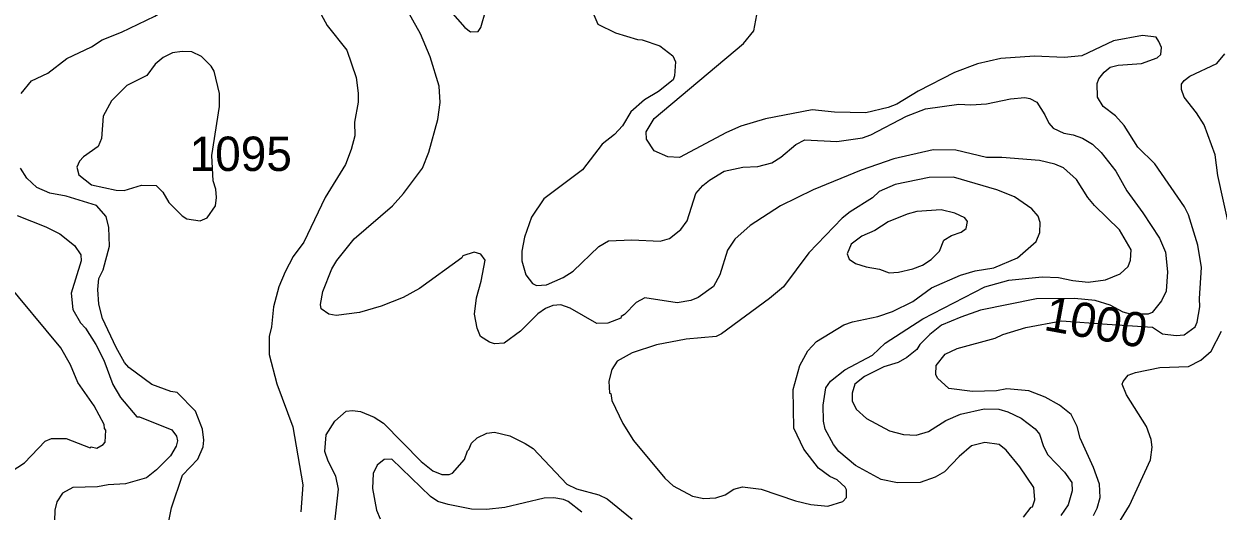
# Model space of a CAD drawing. Extents: x 447.8 to 473.9, y 7733.1 to 7760.8.
# Drawn here: x 464.533 to 467.311, y 7752.592 to 7753.726 of the extents above; entities that cross this region are included whole.
import ezdxf
from ezdxf.enums import TextEntityAlignment as Align

# ---------------------------------------------------------------- set-up
doc = ezdxf.new("R2010")
doc.units = 0
doc.header["$LTSCALE"] = 0.032
doc.layers.add('1', color=7, linetype='Continuous', lineweight=25)
doc.layers.add('2', color=7, linetype='Continuous', lineweight=13)
doc.layers.add('21', color=7, linetype='Continuous')
doc.layers.add('61', color=7, linetype='Continuous')

msp = doc.modelspace()

# ---------------------------------------------------------------- linework, layer by layer
at = {"layer": '1'}
for points in [[(466.2067, 7753.6801), (466.2313, 7753.7094), (466.2382, 7753.7466), (466.2382, 7753.7645), (466.2335, 7753.7801), (466.2144, 7753.7971)], [(467.0215, 7752.5818), (467.0301, 7752.5991), (467.0366, 7752.6242), (467.0349, 7752.6551), (467.0215, 7752.6933), (466.99, 7752.7621), (466.9836, 7752.7893), (466.9691, 7752.817), (466.9423, 7752.8385), (466.909, 7752.8574), (466.8711, 7752.8724), (466.8193, 7752.8764), (466.7958, 7752.8723), (466.74, 7752.8707), (466.6848, 7752.8772), (466.6585, 7752.9014), (466.6543, 7752.9103), (466.655, 7752.9309), (466.6762, 7752.9575), (466.7044, 7752.9708), (466.7922, 7752.9948), (466.8102, 7753.0029), (466.8638, 7753.0191), (466.9471, 7753.0346), (467.0529, 7753.0272), (467.1587, 7753.0198), (467.1817, 7753.0047), (467.2137, 7753.0007), (467.2322, 7753.0026), (467.2575, 7753.0212), (467.2626, 7753.0316), (467.269, 7753.0671), (467.2675, 7753.0868), (467.2722, 7753.1589), (467.2643, 7753.2111), (467.242, 7753.2816), (467.2332, 7753.3004), (467.1638, 7753.4001), (467.1242, 7753.4388), (467.0927, 7753.4893), (467.0721, 7753.5118), (467.0435, 7753.5332), (467.0302, 7753.5556), (467.0294, 7753.587), (467.0333, 7753.5982), (467.0459, 7753.6134), (467.0604, 7753.6248), (467.079, 7753.6299), (467.1328, 7753.6339), (467.1694, 7753.6468), (467.1777, 7753.6547), (467.1795, 7753.6708), (467.1735, 7753.6851), (467.1671, 7753.6946), (467.1354, 7753.6985), (467.0674, 7753.686), (466.9941, 7753.6514), (466.9527, 7753.6474), (466.8842, 7753.6507), (466.8054, 7753.645), (466.7512, 7753.633), (466.698, 7753.6129), (466.6136, 7753.5691), (466.5634, 7753.5391), (466.5437, 7753.531), (466.4919, 7753.5185), (466.4185, 7753.5201), (466.3668, 7753.5256), (466.2582, 7753.505), (466.201, 7753.4878), (466.1672, 7753.4729), (466.0583, 7753.4149), (466.0306, 7753.4161), (465.9988, 7753.4303), (465.9814, 7753.4574), (465.9804, 7753.4746), (465.9993, 7753.5053), (466.2067, 7753.6801)]]:
    msp.add_lwpolyline(points, dxfattribs=at)
at = {"layer": '2'}
for points in [[(464.5267, 7753.5642), (464.5507, 7753.5935), (464.5888, 7753.6108), (464.6325, 7753.6453), (464.6901, 7753.6726), (464.7147, 7753.6885), (464.7601, 7753.7068), (464.8372, 7753.7441), (464.8794, 7753.7697), (464.937, 7753.7924), (464.9565, 7753.8121), (464.9631, 7753.8352), (464.9621, 7753.8724)], [(466.4166, 7752.7474), (466.3971, 7752.7831), (466.3929, 7752.8014), (466.3923, 7752.8387), (466.3986, 7752.8792), (466.4096, 7752.8945), (466.4428, 7752.921), (466.5072, 7752.9548), (466.5362, 7752.9827), (466.624, 7753.0393), (466.7685, 7753.1143), (466.8241, 7753.1295), (466.9016, 7753.1376), (466.9396, 7753.1361), (466.9732, 7753.1284), (467.0085, 7753.125), (467.0493, 7753.1301), (467.0829, 7753.1444), (467.1018, 7753.1617), (467.1071, 7753.1762), (467.1088, 7753.2004), (467.082, 7753.247), (467.0239, 7753.3032), (467.0081, 7753.322), (466.982, 7753.3637), (466.9514, 7753.3906), (466.9312, 7753.3997), (466.8959, 7753.4078), (466.8077, 7753.415), (466.7724, 7753.415), (466.7012, 7753.4319), (466.6483, 7753.4326), (466.5564, 7753.4115), (466.481, 7753.3852), (466.3688, 7753.34), (466.293, 7753.3022), (466.2229, 7753.2568), (466.1872, 7753.2253), (466.1696, 7753.1991), (466.1523, 7753.1422), (466.1374, 7753.1148), (466.1016, 7753.0895), (466.0847, 7753.0825), (466.0528, 7753.077), (465.9778, 7753.0885), (465.9572, 7753.0777), (465.9305, 7753.0497), (465.9228, 7753.0449), (465.922, 7753.0414), (465.8917, 7753.0298), (465.866, 7753.0288), (465.8037, 7753.0647), (465.7817, 7753.0718), (465.7638, 7753.0703), (465.7461, 7753.0639), (465.7282, 7753.0513), (465.688, 7753.0108), (465.6502, 7752.9827), (465.6274, 7752.9814), (465.6159, 7752.9855), (465.5952, 7752.9987), (465.5873, 7753.0178), (465.5813, 7753.0503), (465.5858, 7753.0884), (465.597, 7753.1269), (465.6064, 7753.1758), (465.5963, 7753.1903), (465.5802, 7753.1946), (465.5538, 7753.1858), (465.5517, 7753.1816), (465.4533, 7753.1101), (465.4151, 7753.0894), (465.3638, 7753.0693), (465.314, 7753.054), (465.2595, 7753.0472), (465.2421, 7753.0507), (465.2246, 7753.0629), (465.2227, 7753.0731), (465.2285, 7753.1032), (465.2492, 7753.1556), (465.2612, 7753.1752), (465.3009, 7753.2256), (465.3904, 7753.3023), (465.4161, 7753.331), (465.4604, 7753.3903), (465.475, 7753.4275), (465.4956, 7753.5033), (465.5015, 7753.543), (465.4993, 7753.5809), (465.4782, 7753.6494), (465.4557, 7753.7023), (465.3663, 7753.8621)], [(465.2145, 7753.7664), (465.2388, 7753.7217), (465.2839, 7753.6645), (465.3059, 7753.6013), (465.3108, 7753.5645), (465.3102, 7753.5435), (465.302, 7753.4969), (465.3026, 7753.4656), (465.2943, 7753.4338), (465.2808, 7753.3984), (465.234, 7753.3215), (465.1843, 7753.2181), (465.1595, 7753.1844), (465.1405, 7753.149), (465.1259, 7753.1143), (465.1134, 7753.0676), (465.1089, 7753.0212), (465.1032, 7752.9985), (465.1032, 7752.9562), (465.1212, 7752.8883), (465.1585, 7752.7882), (465.1817, 7752.6535), (465.177, 7752.5907)], [(465.5245, 7753.7559), (465.5591, 7753.7174), (465.5719, 7753.7076), (465.5896, 7753.7083), (465.5959, 7753.7175), (465.6075, 7753.7577)], [(465.8591, 7753.7469), (465.8683, 7753.725), (465.9095, 7753.7049), (465.9602, 7753.6893), (465.9712, 7753.6888), (466.0124, 7753.6746), (466.0427, 7753.6513), (466.049, 7753.6374), (466.0467, 7753.6046), (466.043, 7753.5959)], [(467.3382, 7753.2467), (467.3108, 7753.373), (467.3043, 7753.4214), (467.2786, 7753.4912), (467.2612, 7753.519), (467.232, 7753.5551), (467.2258, 7753.5734), (467.2258, 7753.5854), (467.2318, 7753.5942), (467.2457, 7753.6045), (467.3085, 7753.6337), (467.3265, 7753.6564)], [(466.043, 7753.5959), (466.0092, 7753.5683), (465.9769, 7753.5489), (465.9452, 7753.5212), (465.9256, 7753.4885), (465.9066, 7753.4682)], [(465.9066, 7753.4682), (465.8779, 7753.4458), (465.8328, 7753.3864), (465.7425, 7753.319), (465.7141, 7753.2758), (465.6977, 7753.2295), (465.6916, 7753.197), (465.6916, 7753.1742), (465.7006, 7753.142), (465.7161, 7753.1219), (465.7256, 7753.1169), (465.7486, 7753.1185), (465.7876, 7753.1359), (465.8104, 7753.1507), (465.8706, 7753.2078), (465.8929, 7753.2207), (465.947, 7753.2235), (466.0128, 7753.2203), (466.0349, 7753.2268), (466.0613, 7753.2471), (466.0763, 7753.2676), (466.0963, 7753.3309), (466.1126, 7753.3496), (466.1281, 7753.3624), (466.1621, 7753.3829), (466.2058, 7753.3926), (466.2401, 7753.3943), (466.2732, 7753.4029), (466.2941, 7753.4156), (466.3288, 7753.4455), (466.3495, 7753.456), (466.4238, 7753.452), (466.4842, 7753.4609), (466.503, 7753.4673), (466.586, 7753.5113), (466.6301, 7753.5282), (466.7076, 7753.5392), (466.736, 7753.5376), (466.7727, 7753.5401), (466.8279, 7753.5513), (466.8618, 7753.5545), (466.8733, 7753.552), (466.8894, 7753.5435), (466.9083, 7753.5144), (466.9173, 7753.495), (466.9278, 7753.483), (466.9519, 7753.4718), (466.974, 7753.4679), (466.9959, 7753.4602), (467.0192, 7753.4461), (467.0388, 7753.4265), (467.073, 7753.3835), (467.099, 7753.3374), (467.1364, 7753.2865), (467.1744, 7753.2274), (467.1886, 7753.1945), (467.1937, 7753.1489), (467.1905, 7753.1041), (467.1792, 7753.0816), (467.1579, 7753.0543), (467.1482, 7753.0501), (467.1075, 7753.0505), (467.0903, 7753.0554), (467.0603, 7753.0713), (467.025, 7753.0824), (466.9769, 7753.087), (466.8888, 7753.0863), (466.7587, 7753.0595), (466.7124, 7753.0438), (466.6679, 7753.0246), (466.6404, 7753.0028), (466.6173, 7752.9798), (466.6099, 7752.9683), (466.5872, 7752.9495), (466.5665, 7752.938), (466.5333, 7752.9276), (466.4886, 7752.9054), (466.4658, 7752.8873), (466.4599, 7752.8667), (466.4595, 7752.8486), (466.469, 7752.8293), (466.4935, 7752.808), (466.5467, 7752.7791), (466.5794, 7752.7706), (466.6089, 7752.769), (466.6373, 7752.7775), (466.6778, 7752.8028), (466.7118, 7752.818), (466.7672, 7752.8298), (466.8012, 7752.8297), (466.8218, 7752.8234), (466.8532, 7752.8086), (466.8857, 7752.7837), (466.8953, 7752.7716), (466.9046, 7752.7423)], [(464.8648, 7752.5407), (464.8765, 7752.5997), (464.9018, 7752.6756), (464.9377, 7752.7128), (464.95, 7752.7417), (464.9517, 7752.7573), (464.9485, 7752.7828), (464.9319, 7752.8244), (464.8894, 7752.8681), (464.8744, 7752.8703), (464.8302, 7752.8867), (464.7772, 7752.9266), (464.7672, 7752.9376), (464.7473, 7752.9726), (464.7158, 7753.0406), (464.7073, 7753.0735), (464.7049, 7753.1076), (464.7074, 7753.1337), (464.7172, 7753.1532), (464.7319, 7753.2085), (464.7305, 7753.2524), (464.7247, 7753.2779), (464.7019, 7753.3034), (464.6312, 7753.3246), (464.593, 7753.3317), (464.5631, 7753.3448), (464.5398, 7753.3669), (464.5248, 7753.3904)], [(464.5175, 7753.2798), (464.584, 7753.2538)], [(464.584, 7753.2538), (464.6168, 7753.2374), (464.6509, 7753.21), (464.6655, 7753.1888), (464.6663, 7753.1745), (464.6431, 7753.0996)], [(464.4857, 7752.6727), (464.5346, 7752.7046), (464.5825, 7752.7549), (464.5974, 7752.7608), (464.6315, 7752.761), (464.6869, 7752.7395), (464.6895, 7752.7415), (464.7025, 7752.7388), (464.717, 7752.747), (464.7222, 7752.753), (464.7233, 7752.7805), (464.7201, 7752.7848), (464.72, 7752.7935), (464.6961, 7752.8373), (464.6583, 7752.8911), (464.6413, 7752.9328), (464.6192, 7752.9723), (464.4864, 7753.1315)], [(464.6431, 7753.0996), (464.6468, 7753.0613), (464.6644, 7753.0303), (464.6764, 7753.0176), (464.7003, 7752.9799), (464.7187, 7752.9431), (464.7395, 7752.8869), (464.7574, 7752.8565), (464.7954, 7752.8116), (464.8015, 7752.8114), (464.8773, 7752.7815), (464.8883, 7752.7665), (464.8899, 7752.7561), (464.8875, 7752.7434), (464.8737, 7752.7206), (464.8417, 7752.6885), (464.8183, 7752.6697), (464.7693, 7752.6553), (464.7289, 7752.6535), (464.7044, 7752.6488), (464.6466, 7752.6471), (464.6226, 7752.6337), (464.6097, 7752.614), (464.6047, 7752.5946), (464.603, 7752.5429)], [(467.068, 7752.5448), (467.1047, 7752.6055), (467.1537, 7752.7115), (467.1576, 7752.7408), (467.1553, 7752.759), (467.1448, 7752.789), (467.098, 7752.8625), (467.0881, 7752.8872), (467.09, 7752.8941), (467.1022, 7752.9083), (467.1186, 7752.9149), (467.1757, 7752.926), (467.2424, 7752.929), (467.2712, 7752.9432), (467.2949, 7752.964), (467.3194, 7753.0108)], [(465.2556, 7752.5599), (465.2651, 7752.6431), (465.2584, 7752.6736), (465.2405, 7752.7087), (465.2331, 7752.7306), (465.2361, 7752.77), (465.2565, 7752.8013), (465.2825, 7752.8248), (465.2972, 7752.8266), (465.3161, 7752.8243), (465.348, 7752.8109), (465.3696, 7752.7968), (465.4574, 7752.7074), (465.4844, 7752.6859), (465.5056, 7752.6776), (465.5224, 7752.6776), (465.53, 7752.6804), (465.558, 7752.7123), (465.5647, 7752.7326), (465.5684, 7752.7352), (465.5745, 7752.7501), (465.5871, 7752.7624), (465.6098, 7752.7737), (465.6274, 7752.7761), (465.6631, 7752.7672), (465.6992, 7752.7499), (465.7175, 7752.7375), (465.7963, 7752.6549), (465.8183, 7752.6437), (465.8708, 7752.6304), (465.89, 7752.6208), (465.948, 7752.5733)], [(466.6178, 7752.6591), (466.5652, 7752.6583), (466.5276, 7752.6661), (466.4677, 7752.6983), (466.4288, 7752.7308), (466.4166, 7752.7474)], [(466.8586, 7752.5781), (466.8761, 7752.6011), (466.8797, 7752.6022), (466.8851, 7752.6186), (466.8826, 7752.6471), (466.8496, 7752.6955), (466.8183, 7752.734), (466.8021, 7752.7473), (466.7681, 7752.7521), (466.7374, 7752.7439), (466.709, 7752.7195), (466.6745, 7752.6835), (466.6527, 7752.6709), (466.6178, 7752.6591)], [(466.9046, 7752.7423), (466.9151, 7752.723), (466.9538, 7752.6827), (466.9705, 7752.659), (466.9716, 7752.6391), (466.962, 7752.6071)], [(465.8308, 7752.5896), (465.799, 7752.6142), (465.788, 7752.6196), (465.7657, 7752.623), (465.7432, 7752.6223), (465.6519, 7752.6004), (465.6093, 7752.5959), (465.5742, 7752.5967), (465.5202, 7752.6074), (465.4962, 7752.6149), (465.4789, 7752.6261), (465.3888, 7752.7134), (465.3708, 7752.7126), (465.355, 7752.6992), (465.3454, 7752.6799), (465.3436, 7752.645), (465.3532, 7752.5946), (465.3614, 7752.5746)], [(466.962, 7752.6071), (466.9452, 7752.5823)]]:
    msp.add_lwpolyline(points, dxfattribs=at)
for points in [[(464.9753, 7753.6159), (464.9684, 7753.6272), (464.9463, 7753.6497), (464.9234, 7753.6604), (464.9009, 7753.6619), (464.8788, 7753.6587), (464.8566, 7753.6477), (464.8384, 7753.632), (464.8191, 7753.6055), (464.7727, 7753.5823), (464.7367, 7753.5466), (464.7177, 7753.5109), (464.7137, 7753.459), (464.7055, 7753.4408), (464.6714, 7753.4162), (464.662, 7753.4062), (464.656, 7753.3924), (464.6611, 7753.3743), (464.6904, 7753.351), (464.7474, 7753.3393), (464.7661, 7753.3381), (464.8069, 7753.3502), (464.8405, 7753.3494), (464.856, 7753.3342), (464.87, 7753.3099), (464.9012, 7753.2793), (464.9123, 7753.2725), (464.9429, 7753.2677), (464.9593, 7753.2745), (464.9786, 7753.3022), (464.9813, 7753.322), (464.9797, 7753.3413), (464.9734, 7753.3609), (464.9702, 7753.4193), (464.9877, 7753.5333), (464.9877, 7753.5642)], [(466.8965, 7753.2402), (466.8971, 7753.264), (466.8924, 7753.2783), (466.8778, 7753.2956), (466.8378, 7753.3236), (466.7964, 7753.3395), (466.6955, 7753.3693), (466.6387, 7753.3685), (466.5601, 7753.3524), (466.523, 7753.3357), (466.507, 7753.3208), (466.4549, 7753.2885), (466.4368, 7753.2737), (466.3589, 7753.1928), (466.2997, 7753.1142), (466.2675, 7753.0865), (466.1561, 7753.005), (466.1435, 7752.9986), (466.0738, 7752.9919), (466.0045, 7752.979), (465.9477, 7752.9604), (465.9128, 7752.9412), (465.9005, 7752.9215), (465.8936, 7752.8947), (465.895, 7752.867), (465.8983, 7752.8655), (465.901, 7752.8493), (465.9264, 7752.7963), (465.9513, 7752.7567), (466.0238, 7752.6692), (466.0433, 7752.6509), (466.0882, 7752.6268), (466.1149, 7752.6218), (466.1425, 7752.6228), (466.1646, 7752.6299), (466.1848, 7752.6432), (466.2046, 7752.6487), (466.2483, 7752.6435), (466.3283, 7752.6165), (466.3634, 7752.6075), (466.4033, 7752.6039), (466.4378, 7752.6144), (466.4466, 7752.6242), (466.4466, 7752.642), (466.4438, 7752.6481), (466.425, 7752.6647), (466.4079, 7752.6729), (466.3811, 7752.692), (466.3476, 7752.7363), (466.3241, 7752.7851), (466.3224, 7752.8751), (466.3384, 7752.9308), (466.3565, 7752.9651), (466.3772, 7752.987), (466.4408, 7753.0258), (466.4607, 7753.0326), (466.5194, 7753.0449), (466.5535, 7753.0564), (466.6008, 7753.0801), (466.6445, 7753.1114), (466.7122, 7753.1413), (466.7459, 7753.1509), (466.7894, 7753.1586), (466.8441, 7753.1816), (466.8879, 7753.2194)], [(466.6906, 7753.2338), (466.7137, 7753.2409), (466.7251, 7753.2495), (466.7279, 7753.2662), (466.7221, 7753.2748), (466.6988, 7753.2855), (466.6666, 7753.2932), (466.6102, 7753.2891), (466.5874, 7753.2834), (466.5439, 7753.2656), (466.5128, 7753.245), (466.4825, 7753.2318), (466.4578, 7753.213), (466.4483, 7753.1909), (466.4531, 7753.1786), (466.4674, 7753.1683), (466.4925, 7753.1603), (466.5233, 7753.1554), (466.5457, 7753.1467), (466.5673, 7753.1479), (466.6012, 7753.1556), (466.6232, 7753.1643), (466.6433, 7753.1773), (466.6628, 7753.197), (466.6728, 7753.2225)]]:
    msp.add_lwpolyline(points, close=True, dxfattribs=at)

# ---------------------------------------------------------------- texts
at = {"layer": '21'}
msp.add_text('1095', height=0.08, dxfattribs=at).set_placement((464.9184, 7753.3836))
at = {"layer": '61'}
msp.add_text('1000', height=0.08, rotation=349.546, dxfattribs=at).set_placement((467.0202, 7752.9925), align=Align.CENTER)

doc.saveas('drawing.dxf')
